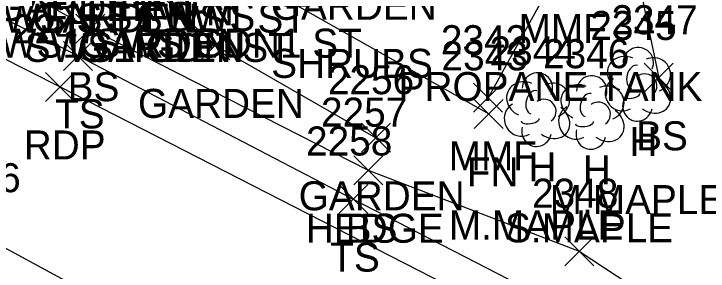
# Model space of a CAD drawing. Extents: x 1499292 to 1501024, y 534584 to 538043.
# Drawn here: x 1499393.02 to 1499440.89, y 537958.35 to 537976.07 of the extents above; entities that cross this region are included whole.
import ezdxf

# ---------------------------------------------------------------- set-up
doc = ezdxf.new("R2010")
doc.units = 0
for name, color, linetype in [('L_A', 7, 'Continuous'), ('L_C', 7, 'Continuous'), ('L_I', 7, 'Continuous'), ('L_TIC', 7, 'Continuous'), ('LAHR', 7, 'Continuous'), ('LAPB', 7, 'Continuous'), ('LDEFAULT', 7, 'Continuous'), ('LELB', 7, 'Continuous'), ('LFNC', 7, 'Continuous'), ('LTD', 7, 'Continuous'), ('P_A', 7, 'Continuous'), ('P_I', 7, 'Continuous'), ('P_TIC', 7, 'Continuous'), ('PET', 7, 'Continuous'), ('PRC', 7, 'Continuous'), ('R_A', 7, 'Continuous')]:
    doc.layers.add(name, color=color, linetype=linetype)

msp = doc.modelspace()

# ---------------------------------------------------------------- linework, layer by layer
at = {"layer": 'L_TIC'}
for points in [[(1499397.285, 537974.056), (1499399.285, 537976.056)], [(1499399.285, 537974.056), (1499397.285, 537976.056)], [(1499405.906, 537972.904), (1499407.906, 537974.904)], [(1499407.906, 537972.904), (1499405.906, 537974.904)], [(1499396.448, 537972.179), (1499398.448, 537974.179)], [(1499398.448, 537972.179), (1499396.448, 537974.179)], [(1499436.487, 537970.67), (1499438.487, 537972.67)], [(1499438.487, 537970.67), (1499436.487, 537972.67)], [(1499424.72, 537969.292), (1499426.72, 537971.292)], [(1499426.72, 537969.292), (1499424.72, 537971.292)], [(1499424.77, 537968.179), (1499426.77, 537970.179)], [(1499426.77, 537968.179), (1499424.77, 537970.179)], [(1499416.988, 537966.537), (1499418.988, 537968.537)], [(1499418.988, 537966.537), (1499416.988, 537968.537)], [(1499416.456, 537964.302), (1499418.456, 537966.302)], [(1499418.456, 537964.302), (1499416.456, 537966.302)], [(1499416.456, 537964.302), (1499418.456, 537966.302)], [(1499418.456, 537964.302), (1499416.456, 537966.302)], [(1499415.424, 537962.314), (1499417.424, 537964.314)], [(1499417.424, 537962.314), (1499415.424, 537964.314)], [(1499431.011, 537958.717), (1499433.011, 537960.717)], [(1499433.011, 537958.717), (1499431.011, 537960.717)]]:
    msp.add_lwpolyline(points, dxfattribs=at)
at = {"layer": 'LAHR'}
msp.add_lwpolyline([(1499417.456, 537965.302), (1499432.011, 537959.717), (1499446.582, 537950.147), (1499455.021, 537950.388), (1499453.53, 537959.367), (1499446.103, 537967.011)], dxfattribs=at)
at = {"layer": 'LAPB'}
msp.add_lwpolyline([(1499402.766, 537977.763), (1499406.906, 537973.904), (1499417.988, 537967.537)], dxfattribs=at)
at = {"layer": 'LDEFAULT'}
msp.add_lwpolyline([(1499430.543, 537979.068), (1499425.72, 537970.292)], dxfattribs=at)
at = {"layer": 'LELB'}
for points in [[(1499318.383, 538015.127), (1499358.346, 537997.221), (1499398.285, 537975.056), (1499417.456, 537965.302)], [(1499317.886, 538011.726), (1499356.952, 537993.674), (1499397.448, 537973.179), (1499416.424, 537963.314), (1499438.648, 537951.874), (1499476.753, 537930.047), (1499490.298, 537922.933), (1499509.513, 537912.513), (1499548.752, 537890.981)], [(1499433.212, 537992.11), (1499437.487, 537971.67)]]:
    msp.add_lwpolyline(points, dxfattribs=at)
at = {"layer": 'LFNC'}
msp.add_lwpolyline([(1499403.414, 537979.895), (1499404.63, 537981.073), (1499406.14, 537980.287), (1499425.77, 537969.179)], dxfattribs=at)
at = {"layer": 'LTD'}
for p, q in [((1499436.032, 537971.274), (1499436.032, 537971.274)), ((1499436.032, 537971.274), (1499436.032, 537971.274)), ((1499429.078, 537969.526), (1499429.078, 537969.526)), ((1499429.078, 537969.526), (1499429.078, 537969.526)), ((1499432.825, 537969.329), (1499432.825, 537969.329)), ((1499432.825, 537969.329), (1499432.825, 537969.329))]:
    msp.add_line(p, q, dxfattribs=at)
for centre in [(1499436.079, 537972.708), (1499429.124, 537970.96), (1499432.872, 537970.763)]:
    msp.add_arc(centre, 1.047, 335.5272, 180.9563, dxfattribs=at)
for centre, major_axis, ratio, start_param, end_param in [((1499435.241, 537971.941), (1.21, -0.512), 0.895232, 1.570796, 4.712389), ((1499437.074, 537971.858), (-1.141, -0.483), 0.949671, 1.570796, 4.712389), ((1499435.824, 537971.733), (-0.208, -0.792), 0.645439, 3.141593, 6.283185), ((1499436.532, 537971.108), (-0.5, 0.667), 0.989748, 3.141593, 6.283185), ((1499428.286, 537970.193), (1.21, -0.512), 0.895232, 1.570796, 4.712389), ((1499430.119, 537970.11), (-1.141, -0.483), 0.949671, 1.570796, 4.712389), ((1499432.033, 537969.996), (1.21, -0.512), 0.895232, 1.570796, 4.712389), ((1499433.866, 537969.913), (-1.141, -0.483), 0.949671, 1.570796, 4.712389), ((1499434.949, 537970.566), (0.584, -1.042), 0.959034, 3.141593, 6.283185), ((1499437.033, 537970.441), (-1.09, 0.792), 0.841452, 1.570796, 4.712389), ((1499428.869, 537969.985), (-0.208, -0.792), 0.645439, 3.141593, 6.283185), ((1499429.578, 537969.36), (-0.5, 0.667), 0.989748, 3.141593, 6.283185), ((1499432.616, 537969.787), (-0.208, -0.792), 0.645439, 3.141593, 6.283185), ((1499435.574, 537970.524), (-0.625, -0.083), 0.423636, 0, 3.141593), ((1499427.994, 537968.818), (0.584, -1.042), 0.959034, 3.141593, 6.283185), ((1499433.325, 537969.163), (-0.5, 0.667), 0.989748, 3.141593, 6.283185), ((1499436.033, 537969.774), (0.265, 1.061), 0.942809, 1.570796, 4.712389), ((1499430.078, 537968.693), (-1.09, 0.792), 0.841452, 1.570796, 4.712389), ((1499431.742, 537968.621), (0.584, -1.042), 0.959034, 3.141593, 6.283185), ((1499433.825, 537968.496), (-1.09, 0.792), 0.841452, 1.570796, 4.712389), ((1499428.619, 537968.776), (-0.625, -0.083), 0.423636, 0, 3.141593), ((1499432.367, 537968.579), (-0.625, -0.083), 0.423636, 0, 3.141593), ((1499429.078, 537968.026), (0.265, 1.061), 0.942809, 1.570796, 4.712389), ((1499432.825, 537967.829), (0.265, 1.061), 0.942809, 1.570796, 4.712389)]:
    msp.add_ellipse(centre, major_axis=major_axis, ratio=ratio, start_param=start_param, end_param=end_param, dxfattribs=at)
at = {"layer": 'P_TIC'}
for points in [[(1499395.207, 537970.039), (1499397.207, 537972.039)], [(1499397.207, 537970.039), (1499395.207, 537972.039)]]:
    msp.add_lwpolyline(points, dxfattribs=at)
at = {"layer": 'PET'}
msp.add_lwpolyline([(1499318.777, 538007.185), (1499356.077, 537991.329), (1499396.207, 537971.039), (1499437.012, 537950.167), (1499476.074, 537929.172), (1499509.306, 537910.677), (1499546.423, 537890.59), (1499566.293, 537879.272), (1499602.082, 537858.76), (1499615.195, 537851.418), (1499643.027, 537835.063), (1499676.234, 537815.623), (1499707.101, 537797.403), (1499725.198, 537785.865), (1499749.466, 537768.587), (1499768.247, 537754.161), (1499782.48, 537740.777), (1499805.279, 537716.472), (1499820.533, 537699.08)], dxfattribs=at)
at = {"layer": 'PRC'}
msp.add_lwpolyline([(1499314.647, 537995.238), (1499351.896, 537980.059), (1499390.853, 537960.785), (1499432.771, 537938.063), (1499470.255, 537918.917), (1499503.529, 537899.736), (1499550.301, 537873.589), (1499594.281, 537849.334), (1499631.071, 537828.01), (1499665.93, 537807.267), (1499699.614, 537786.782), (1499728.317, 537767.815), (1499774.937, 537731.181), (1499796.918, 537710.716), (1499813.912, 537693.068)], dxfattribs=at)

# ---------------------------------------------------------------- texts
at = {"layer": 'L_A'}
for s, p in [('GARDEN', (1499391.661, 537975.573)), ('GARDEN', (1499410.738, 537975.662)), ('FN', (1499404.621, 537975.287)), ('FN', (1499404.621, 537975.287)), ('GARDEN', (1499394.283, 537974.785)), ('FN', (1499401.894, 537974.895)), ('MMF', (1499427.827, 537974.068)), ('GARDEN', (1499397.557, 537973.055)), ('GARDEN', (1499397.435, 537972.763)), ('BS', (1499396.726, 537970.056)), ('GARDEN', (1499401.576, 537968.904)), ('TS', (1499395.857, 537968.179)), ('BS', (1499435.928, 537966.67)), ('H', (1499435.465, 537966.274)), ('MMF', (1499423.004, 537965.292)), ('H', (1499428.511, 537964.526)), ('FN', (1499424.25, 537964.179)), ('H', (1499432.258, 537964.329)), ('GARDEN', (1499412.658, 537962.537)), ('HEDGE', (1499413.156, 537960.302)), ('BS', (1499415.897, 537960.302)), ('TS', (1499414.834, 537958.314))]:
    msp.add_text(s, height=2, dxfattribs=at).set_placement(p)
at = {"layer": 'L_C'}
for s, p in [('LILAC', (1499398.078, 537975.677)), ('SHRUBS', (1499410.761, 537971.662)), ('PROPANE TANK', (1499419.551, 537970.068)), ('M.MAPLE', (1499429.969, 537962.274)), ('M.MAPLE', (1499423.015, 537960.526)), ('S.MAPLE', (1499426.888, 537960.329))]:
    msp.add_text(s, height=2, dxfattribs=at).set_placement(p)
at = {"layer": 'L_I'}
for s, p in [('2347', (1499434.227, 537974.67)), ('2345', (1499432.773, 537974.274)), ('2342', (1499422.461, 537973.292)), ('2343', (1499422.51, 537972.179)), ('2344', (1499425.818, 537972.526)), ('2346', (1499429.51, 537972.329)), ('2256', (1499414.673, 537970.537)), ('2257', (1499414.196, 537968.302)), ('2257', (1499414.196, 537968.302)), ('2258', (1499413.164, 537966.314)), ('2348', (1499428.752, 537962.717))]:
    msp.add_text(s, height=2, dxfattribs=at).set_placement(p)
at = {"layer": 'P_A'}
msp.add_text('RDP', height=2, dxfattribs=at).set_placement((1499393.695, 537966.039))
at = {"layer": 'P_I'}
for s, p in [('2247', (1499392.947, 537974.039)), ('2246', (1499387.538, 537963.785))]:
    msp.add_text(s, height=2, dxfattribs=at).set_placement(p)
at = {"layer": 'R_A'}
for s, p in [('GDN SWS ST SWS1 ST', (1499383.81, 537974.785)), ('GDN SWS ST SWS1 ST', (1499383.81, 537974.785)), ('FN ST SWS', (1499395.099, 537974.895)), ('SWS1 SWS GDN1 ST', (1499390.266, 537973.055)), ('SWS1 SWS GDN1 ST', (1499390.266, 537973.055)), ('SWS1 GDN ST', (1499393.766, 537972.763))]:
    msp.add_text(s, height=2, dxfattribs=at).set_placement(p)

doc.saveas('drawing.dxf')
